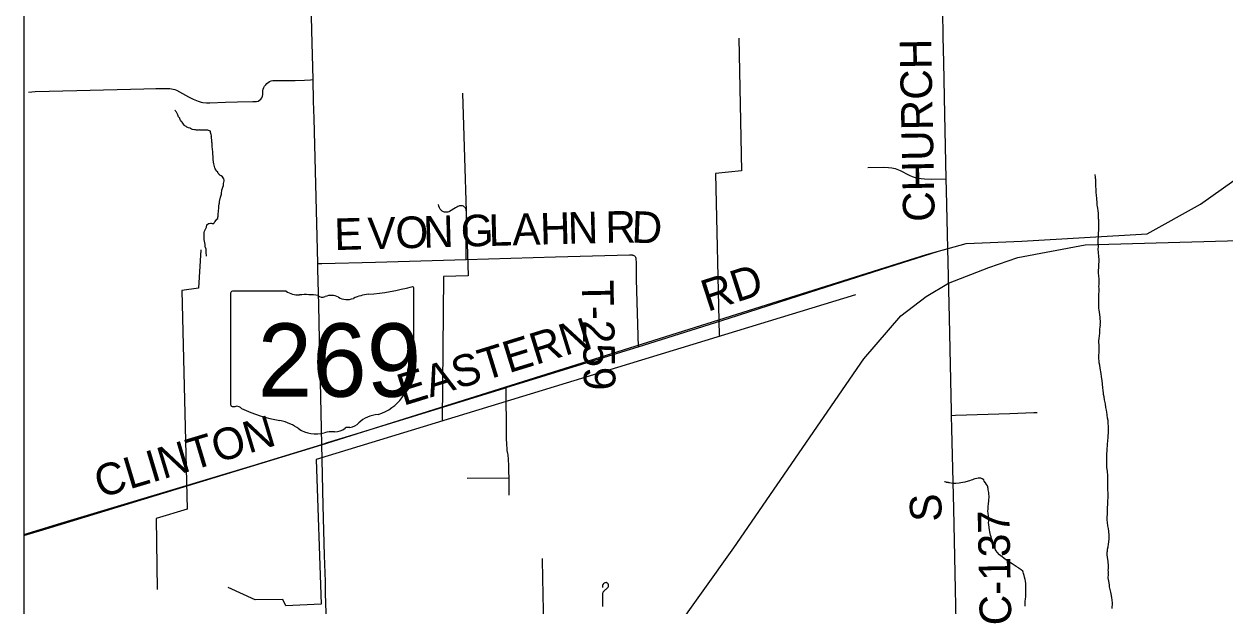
# Model space of a CAD drawing. Extents: x -12 to 34, y 0 to 22.
# Drawn here: x 2.1 to 4.257, y 16.174 to 17.22 of the extents above; entities that cross this region are included whole.
import ezdxf

# ---------------------------------------------------------------- set-up
doc = ezdxf.new("R2010")
doc.units = 0
for name, color, linetype in [('GM_X_Airport_Location_Class_2', 7, 'Continuous'), ('GM_X_Airport_Location_Class_3', 7, 'Continuous'), ('GM_X_Corporation', 7, 'Continuous'), ('GM_X_County_Road', 7, 'Continuous'), ('GM_X_County_Road_Text', 7, 'Continuous'), ('GM_X_Major_Lake', 7, 'Continuous'), ('GM_X_Major_River', 7, 'Continuous'), ('GM_X_Minor_Lake', 7, 'Continuous'), ('GM_X_Township_Road_Text', 7, 'Continuous'), ('GM_X_Township_Text', 7, 'Continuous')]:
    doc.layers.add(name, color=color, linetype=linetype)

msp = doc.modelspace()

# ---------------------------------------------------------------- linework, layer by layer
at = {"layer": 'GM_X_Airport_Location_Class_2'}
for points in [[(2.1, 20.9), (2.1, 15.613), (2.1373, 15.5975), (2.1605, 15.5875), (2.1965, 15.5592), (2.2165, 15.5455), (2.2203, 15.5426), (2.2262, 15.4696), (2.2577, 15.2632), (2.3604, 14.1215)], [(2.1, 17.9664), (2.1, 15.613), (2.1373, 15.5975), (2.1605, 15.5875), (2.1965, 15.5592), (2.2165, 15.5455), (2.2203, 15.5426), (2.2262, 15.4696), (2.2577, 15.2632), (2.3604, 14.1215)]]:
    msp.add_lwpolyline(points, dxfattribs=at)
at = {"layer": 'GM_X_Airport_Location_Class_3'}
for points in [[(3.7582, 16.9413), (3.7576, 16.9704), (3.7557, 17.0573), (3.7539, 17.1502), (3.7527, 17.1967), (3.7517, 17.2433), (3.7501, 17.3178)], [(3.7611, 16.8161), (3.7588, 16.9203), (3.7582, 16.9413)], [(3.2039, 16.6396), (3.3203, 16.6759), (3.3677, 16.6909), (3.5276, 16.7425), (3.6402, 16.7785), (3.744, 16.8114), (3.753, 16.8139), (3.7611, 16.8161)], [(3.7675, 16.5162), (3.7675, 16.5239), (3.7653, 16.6352), (3.7638, 16.6914), (3.7611, 16.8161)], [(2.9666, 16.5661), (3.1748, 16.6305), (3.2039, 16.6396)], [(2.6356, 16.4641), (2.6457, 16.4672), (2.7051, 16.4857), (2.9638, 16.5652), (2.9666, 16.5661)], [(3.788, 16.0606), (3.7843, 16.0645), (3.7816, 16.0677), (3.7803, 16.0697), (3.7794, 16.0715), (3.7785, 16.0737), (3.7779, 16.076), (3.7777, 16.0782), (3.7772, 16.0844), (3.7766, 16.1155), (3.7735, 16.2618), (3.7716, 16.349), (3.7682, 16.4923), (3.7675, 16.5162)], [(2.1, 16.3023), (2.1664, 16.3222), (2.512, 16.426), (2.6356, 16.4641)]]:
    msp.add_lwpolyline(points, dxfattribs=at)
at = {"layer": 'GM_X_Corporation'}
for points in [[(2.1, 16.3006), (2.1396, 16.3122), (2.6348, 16.4631), (3.7224, 16.8052), (3.7941, 16.825), (3.8937, 16.8293), (4.1193, 16.8423), (4.2152, 16.8961), (4.3122, 16.9647)], [(2.8614, 14.9446), (2.8237, 15.0402), (2.7924, 15.0967), (2.7435, 15.1932), (2.7326, 15.2135), (2.7266, 15.2424), (2.7245, 15.2828), (2.7326, 15.3249), (2.7503, 15.3643), (2.8291, 15.4899), (3.0486, 15.8188), (3.3759, 16.2779), (3.6102, 16.618), (3.6764, 16.6954), (3.7218, 16.7297), (3.762, 16.7538), (3.8349, 16.7817), (3.8869, 16.8002), (4.008, 16.8225), (4.8175, 16.8457)]]:
    msp.add_lwpolyline(points, dxfattribs=at)
at = {"layer": 'GM_X_Major_Lake'}
for points in [[(2.6356, 16.4641), (2.6324, 16.6058), (2.6315, 16.6524), (2.63, 16.7145), (2.6285, 16.7797), (2.6282, 16.7889), (2.6277, 16.8138), (2.6216, 17.0497), (2.6207, 17.0808), (2.6198, 17.1197), (2.6177, 17.2081), (2.6154, 17.2856), (2.6139, 17.3349), (2.6126, 17.391), (2.6114, 17.4595), (2.6088, 17.546), (2.6067, 17.6427), (2.6061, 17.683), (2.6057, 17.7025), (2.6057, 17.7322)], [(2.6436, 16.1442), (2.6423, 16.1961), (2.6419, 16.2178), (2.64, 16.2643), (2.6377, 16.3543), (2.6356, 16.4641)]]:
    msp.add_lwpolyline(points, dxfattribs=at)
at = {"layer": 'GM_X_Major_River'}
for p in [(2.8965, 16.4036), (2.9725, 16.373)]:
    msp.add_line(p, (2.972, 16.4041), dxfattribs=at)
for points in [[(2.108, 17.0973), (2.1203, 17.0981), (2.1948, 17.0998), (2.3157, 17.1028), (2.3373, 17.1035), (2.356, 17.1036), (2.3621, 17.1034), (2.3652, 17.103), (2.3683, 17.1024), (2.3712, 17.1016), (2.3741, 17.1005), (2.3798, 17.0979), (2.396, 17.0888), (2.4043, 17.0846), (2.4129, 17.081), (2.4188, 17.0791), (2.4218, 17.0785), (2.428, 17.0778), (2.4342, 17.0777), (2.4621, 17.0789), (2.4837, 17.0796), (2.5117, 17.0801), (2.5179, 17.0805), (2.5209, 17.0811), (2.5236, 17.0825), (2.5259, 17.0845), (2.5276, 17.0871), (2.5286, 17.09), (2.5291, 17.0931), (2.5295, 17.0993), (2.5301, 17.1024), (2.5311, 17.1053), (2.5326, 17.108), (2.5345, 17.1104), (2.5366, 17.1127), (2.539, 17.1147), (2.5416, 17.1163), (2.5445, 17.1174), (2.5475, 17.1179), (2.5512, 17.118), (2.5875, 17.1182), (2.6044, 17.1187), (2.6151, 17.1194), (2.6198, 17.1197)], [(3.6168, 16.9619), (3.6448, 16.9622), (3.6542, 16.9619), (3.6604, 16.9613), (3.6634, 16.9607), (3.6665, 16.9599), (3.6694, 16.9589), (3.6751, 16.9565), (3.6917, 16.9477), (3.6967, 16.9455), (3.7004, 16.9441), (3.7037, 16.9431), (3.7077, 16.9423), (3.7127, 16.9417), (3.7188, 16.9413), (3.7312, 16.9409), (3.7582, 16.9413)], [(2.8948, 16.7964), (2.8953, 16.8752), (2.8953, 16.8799), (2.8953, 16.8828), (2.895, 16.8846), (2.8947, 16.8862), (2.8941, 16.8877), (2.8935, 16.8889), (2.8929, 16.8896), (2.8919, 16.8907), (2.8911, 16.8913), (2.8899, 16.8921), (2.8885, 16.8927), (2.8872, 16.8929), (2.8857, 16.893), (2.8847, 16.893), (2.883, 16.8927), (2.8818, 16.8922), (2.8802, 16.8916), (2.8783, 16.8906), (2.8756, 16.8891), (2.8649, 16.8827), (2.8635, 16.882), (2.862, 16.8816), (2.859, 16.8812), (2.8577, 16.8812), (2.8559, 16.8815), (2.854, 16.8822), (2.852, 16.8832), (2.8505, 16.8843), (2.8492, 16.8856), (2.8484, 16.8866), (2.8468, 16.8893), (2.8458, 16.8922), (2.8452, 16.8953)], [(2.6282, 16.7889), (2.6355, 16.7891), (2.7319, 16.7918), (2.8948, 16.7964)], [(2.8948, 16.7964), (3.0554, 16.801), (3.1885, 16.8048), (3.1899, 16.8047), (3.191, 16.8047), (3.1925, 16.8046), (3.1934, 16.8045), (3.1942, 16.8043), (3.1953, 16.804), (3.1961, 16.8036), (3.1973, 16.8029), (3.1979, 16.8024)], [(3.1979, 16.8024), (3.1986, 16.8016), (3.1993, 16.8004), (3.1996, 16.7999), (3.1997, 16.7993), (3.2, 16.7982), (3.2001, 16.7971), (3.2002, 16.7961), (3.2002, 16.795), (3.2003, 16.7928), (3.2007, 16.7606), (3.2039, 16.6396)], [(2.972, 16.4041), (2.9719, 16.4152), (2.9718, 16.4265), (2.9712, 16.4366), (2.971, 16.4396), (2.9707, 16.4424), (2.9702, 16.4454), (2.9699, 16.4475), (2.9689, 16.4531), (2.9684, 16.4577), (2.9681, 16.4624), (2.9678, 16.4677), (2.9677, 16.4714), (2.9675, 16.4807), (2.9666, 16.5661)], [(3.7675, 16.5162), (3.7749, 16.5165), (3.8725, 16.5197), (3.9156, 16.5214), (3.9218, 16.5213)], [(3.0398, 15.8619), (3.0388, 15.8935), (3.0369, 15.9988), (3.0348, 16.1041), (3.0337, 16.1661), (3.0332, 16.1939), (3.0321, 16.2559), (3.0321, 16.259)], [(3.1407, 16.1727), (3.1407, 16.1926), (3.1407, 16.1948), (3.1407, 16.1959), (3.1409, 16.1969), (3.141, 16.1977), (3.1413, 16.1984), (3.142, 16.1995), (3.1428, 16.2005), (3.1432, 16.201), (3.1439, 16.2016), (3.1445, 16.2023), (3.1455, 16.2031), (3.1465, 16.2039), (3.1492, 16.2061), (3.1498, 16.2067), (3.1502, 16.2072), (3.1508, 16.2084), (3.1509, 16.209), (3.151, 16.2098), (3.151, 16.211), (3.1509, 16.2118), (3.1507, 16.2125), (3.1504, 16.2131), (3.15, 16.2137), (3.1493, 16.2144), (3.1487, 16.2148), (3.1477, 16.2154), (3.147, 16.2156), (3.1464, 16.2156), (3.1448, 16.2155), (3.1441, 16.2153), (3.1432, 16.2148), (3.1423, 16.2142), (3.1415, 16.2133), (3.141, 16.2125), (3.1408, 16.212), (3.1403, 16.2104), (3.1402, 16.2098), (3.1402, 16.2089), (3.1401, 16.208), (3.1401, 16.207)]]:
    msp.add_lwpolyline(points, dxfattribs=at)
at = {"layer": 'GM_X_Minor_Lake'}
for points in [[(3.3851, 17.1943), (3.3897, 16.956), (3.3434, 16.9512), (3.3498, 16.6597)], [(2.8882, 17.0954), (2.8986, 16.7671), (2.8542, 16.7657), (2.8521, 16.5061)], [(2.3993, 17.0317), (2.3986, 17.0324), (2.396, 17.0332), (2.3944, 17.0336), (2.3929, 17.0344), (2.3914, 17.0352), (2.3892, 17.0367), (2.3881, 17.0379), (2.3866, 17.0398), (2.3843, 17.0429), (2.3825, 17.0452), (2.3814, 17.0467), (2.381, 17.0479), (2.3803, 17.0486), (2.3799, 17.0494), (2.3799, 17.0505), (2.3788, 17.0517), (2.378, 17.0528), (2.3773, 17.0544), (2.3766, 17.0563), (2.3762, 17.0574), (2.3751, 17.0586), (2.3747, 17.0597), (2.374, 17.0609), (2.3729, 17.0624), (2.3721, 17.0636), (2.371, 17.0647)], [(2.4282, 16.8022), (2.4276, 16.8098), (2.4273, 16.8152), (2.4262, 16.8178), (2.4258, 16.8194), (2.4255, 16.8235), (2.4241, 16.8323), (2.4242, 16.838), (2.4238, 16.8391), (2.4239, 16.8448), (2.4243, 16.8475), (2.4263, 16.8509), (2.4282, 16.8547), (2.429, 16.8584), (2.4317, 16.8611), (2.4332, 16.861), (2.4355, 16.8614), (2.4367, 16.8614), (2.4382, 16.861), (2.4401, 16.8609), (2.4412, 16.8613), (2.4416, 16.8628), (2.4435, 16.8647), (2.4466, 16.8688), (2.4482, 16.8703), (2.4486, 16.8726), (2.449, 16.8741), (2.449, 16.8768), (2.4499, 16.8836), (2.4503, 16.8889), (2.4504, 16.8919), (2.4508, 16.8969), (2.4512, 16.8976), (2.4512, 16.898), (2.4516, 16.9003), (2.4533, 16.9082), (2.4552, 16.9139), (2.4553, 16.915), (2.4557, 16.9207), (2.4577, 16.9264), (2.4585, 16.9294), (2.4589, 16.9302), (2.4589, 16.9332), (2.459, 16.9351), (2.4598, 16.9378), (2.4598, 16.9389), (2.4591, 16.9416), (2.458, 16.9431), (2.4568, 16.945), (2.4542, 16.9466), (2.4523, 16.9481), (2.4512, 16.9489), (2.4505, 16.9497), (2.4497, 16.9508), (2.4486, 16.952), (2.4482, 16.9531), (2.446, 16.9554), (2.4456, 16.9569), (2.4438, 16.9596), (2.4431, 16.9612), (2.4427, 16.9638), (2.4413, 16.9684), (2.4409, 16.9711), (2.4406, 16.9714), (2.4406, 16.9726), (2.4402, 16.9753), (2.4399, 16.9783), (2.44, 16.9825), (2.4396, 16.984), (2.4396, 16.9863), (2.4397, 16.9882), (2.4393, 16.9905), (2.439, 16.9939), (2.4383, 17), (2.438, 17.0026), (2.438, 17.0053), (2.4377, 17.0072), (2.4377, 17.0106), (2.437, 17.0148), (2.437, 17.0167), (2.4367, 17.0175), (2.4371, 17.0186), (2.4363, 17.0209), (2.4356, 17.0247), (2.4353, 17.027), (2.4338, 17.0278), (2.4319, 17.0282), (2.4308, 17.0286), (2.4281, 17.0286), (2.4266, 17.029), (2.4179, 17.0291), (2.4164, 17.0291), (2.4149, 17.0292), (2.413, 17.0288), (2.4099, 17.0288), (2.4084, 17.0292), (2.4065, 17.0293), (2.4027, 17.0301), (2.4016, 17.0305), (2.4012, 17.0309), (2.3993, 17.0317)], [(4.0373, 16.5854), (4.0366, 16.5912), (4.0345, 16.6011), (4.0342, 16.6064), (4.0331, 16.6106), (4.0328, 16.614), (4.0324, 16.6178), (4.0327, 16.6356), (4.0327, 16.6379), (4.0328, 16.6429), (4.0325, 16.6474), (4.0325, 16.6501), (4.033, 16.6542), (4.0339, 16.6637), (4.0344, 16.6706), (4.0348, 16.6755), (4.0352, 16.6781), (4.0349, 16.6797), (4.0353, 16.6827), (4.0353, 16.6857), (4.035, 16.6895), (4.0347, 16.693), (4.034, 16.6971), (4.0333, 16.7021), (4.033, 16.7051), (4.0326, 16.7086), (4.0325, 16.7222), (4.0326, 16.7325), (4.0331, 16.7405), (4.0328, 16.7446), (4.0324, 16.7473), (4.0329, 16.7518), (4.033, 16.7613), (4.0324, 16.767), (4.032, 16.7716), (4.0317, 16.7747), (4.0317, 16.7769), (4.0322, 16.7815), (4.0323, 16.7876), (4.0327, 16.7929), (4.0328, 16.7967), (4.0325, 16.8012), (4.0318, 16.8096), (4.0315, 16.8145), (4.0316, 16.8206), (4.0313, 16.8267), (4.0316, 16.8419), (4.0321, 16.851), (4.0322, 16.8593), (4.0323, 16.8677), (4.032, 16.8692), (4.032, 16.8723), (4.0317, 16.8753), (4.0317, 16.8798), (4.031, 16.884), (4.0304, 16.8886), (4.03, 16.8916), (4.0297, 16.8939), (4.0297, 16.8951), (4.0293, 16.8966), (4.0294, 16.9004), (4.0291, 16.9038), (4.0287, 16.9069), (4.028, 16.911), (4.0281, 16.9133), (4.0277, 16.9156), (4.0278, 16.9205), (4.0272, 16.9297), (4.0273, 16.9354), (4.0269, 16.9399), (4.0266, 16.9418), (4.0263, 16.9445), (4.0263, 16.9456), (4.0259, 16.9479), (4.0256, 16.9491)], [(2.4181, 16.8138), (2.4135, 16.745), (2.3836, 16.7407), (2.3932, 16.3474), (2.3374, 16.3308), (2.3392, 16.2031)], [(3.5951, 16.7327), (2.6254, 16.437), (2.634, 16.1771), (2.5706, 16.1737), (2.5652, 16.1855), (2.5159, 16.1845), (2.4671, 16.2071)], [(4.0565, 16.1689), (4.0567, 16.1784), (4.0564, 16.1849), (4.0557, 16.1883), (4.055, 16.1925), (4.0539, 16.1986), (4.0529, 16.2032), (4.0518, 16.2081), (4.0515, 16.2119), (4.0504, 16.2184), (4.0494, 16.2245), (4.0495, 16.2302), (4.0491, 16.2317), (4.0495, 16.2328), (4.0495, 16.2347), (4.0496, 16.2359), (4.0492, 16.2378), (4.0496, 16.2408), (4.0497, 16.2458), (4.0491, 16.2534), (4.048, 16.2613), (4.0473, 16.2655), (4.0474, 16.2701), (4.0478, 16.2724), (4.0482, 16.2758), (4.0491, 16.2799), (4.0499, 16.2849), (4.0503, 16.289), (4.0508, 16.2943), (4.0509, 16.3012), (4.0502, 16.3076), (4.0496, 16.3126), (4.0485, 16.3179), (4.0478, 16.3236), (4.0475, 16.3282), (4.0476, 16.3335), (4.048, 16.3384), (4.0482, 16.3513), (4.0487, 16.3555), (4.049, 16.3756), (4.0487, 16.3832), (4.0488, 16.3935), (4.0486, 16.4011), (4.0483, 16.4083), (4.0477, 16.4155), (4.047, 16.4231), (4.0467, 16.43), (4.047, 16.4456), (4.0475, 16.4539), (4.048, 16.4645), (4.0489, 16.4763), (4.0495, 16.4881), (4.05, 16.4964), (4.0493, 16.5025), (4.0494, 16.5067), (4.0479, 16.5112), (4.0473, 16.5169), (4.0466, 16.5219), (4.0459, 16.5257), (4.0452, 16.5306), (4.0441, 16.5371), (4.0427, 16.544), (4.042, 16.5497), (4.041, 16.5535), (4.0406, 16.5565), (4.0399, 16.5607), (4.0396, 16.5657), (4.039, 16.5721), (4.0383, 16.5786), (4.0373, 16.5854)], [(3.8326, 16.3878), (3.8323, 16.3897), (3.8304, 16.392), (3.8286, 16.3947), (3.826, 16.3982), (3.8256, 16.4001), (3.8226, 16.402), (3.8215, 16.4028), (3.8203, 16.4032), (3.8192, 16.4036), (3.8173, 16.4036), (3.8154, 16.4033), (3.8128, 16.4029), (3.8097, 16.4022), (3.8074, 16.4015), (3.8051, 16.4004), (3.8029, 16.3996), (3.7998, 16.3985), (3.7975, 16.3982), (3.7914, 16.396), (3.7876, 16.3953), (3.7842, 16.395), (3.7812, 16.3946), (3.7751, 16.394), (3.7717, 16.394), (3.7668, 16.3944), (3.7641, 16.3949), (3.7626, 16.3949), (3.7622, 16.3953), (3.7603, 16.3957), (3.7588, 16.3957), (3.7577, 16.3961), (3.7562, 16.3965), (3.755, 16.3969)], [(3.9, 16.1734), (3.9001, 16.1818), (3.9006, 16.1867), (3.901, 16.1901), (3.9014, 16.1913), (3.9014, 16.1935), (3.9011, 16.1989), (3.9012, 16.2065), (3.9009, 16.2103), (3.901, 16.2152), (3.9006, 16.2167), (3.9003, 16.2186), (3.8999, 16.2213), (3.8989, 16.2255), (3.8982, 16.2285), (3.8971, 16.2323), (3.8964, 16.2346), (3.8956, 16.2362), (3.8926, 16.2385), (3.8907, 16.2396), (3.8889, 16.2412), (3.8881, 16.2423), (3.8836, 16.2443), (3.8802, 16.247), (3.8765, 16.2493), (3.8735, 16.2513), (3.8716, 16.2525), (3.8701, 16.2536), (3.8682, 16.2548), (3.866, 16.2563), (3.8648, 16.2567), (3.8637, 16.2579), (3.8618, 16.2594), (3.8588, 16.2617), (3.8562, 16.2637), (3.854, 16.2656), (3.8495, 16.2702), (3.8476, 16.2729), (3.8462, 16.276), (3.844, 16.2821), (3.8422, 16.2882), (3.8411, 16.2916), (3.8396, 16.2947), (3.8389, 16.2977), (3.8378, 16.3008), (3.8364, 16.3069), (3.8357, 16.3103), (3.8354, 16.3149), (3.8347, 16.3198), (3.8343, 16.3229), (3.8344, 16.3259), (3.8341, 16.3301), (3.8341, 16.3331), (3.8338, 16.3358), (3.8335, 16.3403), (3.8331, 16.3441), (3.8332, 16.3479), (3.8336, 16.3498), (3.8336, 16.3513), (3.8341, 16.3586), (3.8345, 16.3612), (3.8345, 16.3631), (3.8349, 16.3642), (3.835, 16.3692), (3.835, 16.3715), (3.8347, 16.3741), (3.8344, 16.3775), (3.8337, 16.3825), (3.8333, 16.3848), (3.833, 16.3867), (3.8326, 16.3871), (3.8326, 16.3878)]]:
    msp.add_lwpolyline(points, dxfattribs=at)
at = {"layer": 'GM_X_Township_Text'}
for p, q in [((2.8011, 16.6395), (2.8011, 16.7442)), ((2.4715, 16.7358), (2.4715, 16.5356)), ((2.5713, 16.7392), (2.4748, 16.7392)), ((2.8011, 16.6395), (2.8011, 16.6395))]:
    msp.add_line(p, q, dxfattribs=at)
for centre, major_axis, start_param, end_param in [((2.6837, 17.012), (0.3495, 0), 4.814394, 5.042369), ((2.7975, 16.7446), (0.00367, 0), 6.141152, 7.989035), ((2.4753, 16.7362), (0.00382, 0), 1.712693, 3.28349), ((2.5943, 16.7624), (0.037, 0), 4.042523, 4.731795), ((2.6066, 16.6268), (0.133, 0), 1.404758, 1.657858), ((2.6367, 16.7372), (0.0107, 0), 3.836095, 5.185415), ((2.6524, 16.7141), (0.0222, 0), 0.950623, 2.079405), ((2.6811, 16.7458), (0.0267, 0), 4.081561, 5.145723), ((2.7283, 16.6781), (0.0703, 0), 1.699011, 2.107814), ((2.8003, 16.6318), (0.00568, 0), 1.883978, 3.671073), ((2.7972, 16.6391), (0.00393, 0), 5.05454, 6.418171), ((2.7641, 16.6186), (0.0341, 0), 5.934695, 6.695948), ((2.7033, 16.5823), (0.0874, 0), 5.101752, 6.440018), ((2.8143, 16.5957), (0.0248, 0), 2.387724, 3.262537), ((2.4753, 16.5352), (0.00385, 0), 3.00124, 4.508301), ((2.4759, 16.5557), (0.0294, 0), 4.665946, 4.897461), ((2.4819, 16.5241), (0.0106, 0), 0.519207, 1.627899), ((2.6158, 16.7039), (0.2524, 0), 4.195997, 4.488961), ((2.5405, 16.4457), (0.079, 0), 0.823519, 1.323587), ((2.7402, 16.4794), (0.0479, 0), 1.647645, 2.488434), ((2.6259, 16.5231), (0.0501, 0), 4.026481, 4.996735), ((2.6549, 16.4539), (0.0412, 0), 1.495662, 1.94098), ((2.6585, 16.5081), (0.0267, 0), 4.691044, 5.507374), ((2.6827, 16.4887), (0.00752, 0), 1.147584, 2.315152), ((2.6795, 16.5162), (0.0282, 0), 4.937069, 5.64225)]:
    msp.add_ellipse(centre, major_axis=major_axis, ratio=0.8, start_param=start_param, end_param=end_param, dxfattribs=at)

# ---------------------------------------------------------------- texts
at = {"layer": 'GM_X_County_Road'}
for s, height, rotation, p in [('CHURCH', 0.05682, 91.1467, (3.7375, 16.8645)), ('RD', 0.05682, 17.9697, (3.3289, 16.7021)), ('EASTERN', 0.05682, 17.1812, (2.7819, 16.5331)), ('CLINTON', 0.05682, 16.7127, (2.2369, 16.3673)), ('S', 0.0568, 91.283, (3.7501, 16.3256)), ('C-137', 0.05682, 91.1032, (3.8753, 16.1394))]:
    msp.add_text(s, height=height, rotation=rotation, dxfattribs=at).set_placement(p)
at = {"layer": 'GM_X_County_Road_Text'}
for s, height, rotation, p in [('E', 0.0568, 1.5345, (2.6585, 16.8132)), ('V', 0.0568, 1.5316, (2.7185, 16.8148)), ('O', 0.0568, 1.5316, (2.7685, 16.8161)), ('N', 0.0568, 1.5316, (2.8184, 16.8175)), ('G', 0.0568, 1.5316, (2.8859, 16.8193)), ('L', 0.0568, 1.5326, (2.9359, 16.8206)), ('A', 0.0568, 1.5316, (2.9784, 16.8217)), ('H', 0.0568, 1.5306, (3.0284, 16.8231)), ('N', 0.0568, 1.5362, (3.0783, 16.8244)), ('R', 0.0568, 0.8002, (3.1456, 16.8262)), ('D', 0.0568, 357.6972, (3.1915, 16.8269)), ('T-259', 0.05682, 271.1227, (3.103, 16.7589))]:
    msp.add_text(s, height=height, rotation=rotation, dxfattribs=at).set_placement(p)
at = {"layer": 'GM_X_Township_Road_Text'}
for s in ['s', 'r']:
    msp.add_text(s, height=0.000189, dxfattribs=at).set_placement((2.6326, 16.6224))
msp.add_text('269', height=0.000189, rotation=0, dxfattribs=at).set_placement((2.5658, 16.6086))
at = {"layer": 'GM_X_Township_Text'}
msp.add_text('269', height=0.13184, dxfattribs=at).set_placement((2.52, 16.5497))

doc.saveas('drawing.dxf')
